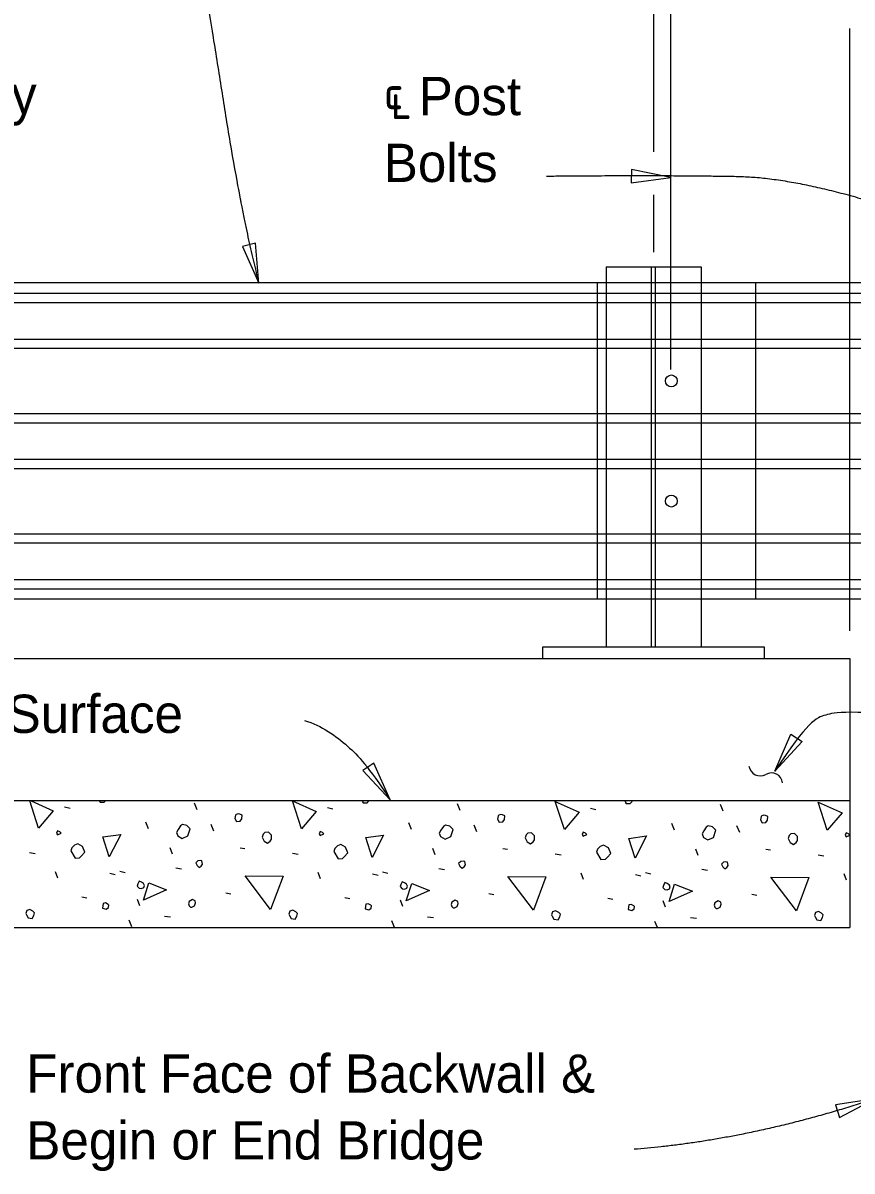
# Model space of a CAD drawing. Extents: x 21526.6 to 21595.9, y 56117 to 56157.3.
# Drawn here: x 21549.82 to 21554.19, y 56132.51 to 56138.56 of the extents above; entities that cross this region are included whole.
import ezdxf

# ---------------------------------------------------------------- set-up
doc = ezdxf.new("R2010")
doc.units = 0
for name, color, linetype in [('AdhocPoint_dp', 7, 'Continuous'), ('Border', 7, 'Continuous'), ('Patterning', 7, 'Continuous'), ('PlotBorder_dp', 7, 'Continuous'), ('SheetBorder_dp', 7, 'Continuous'), ('TextMisc', 7, 'Continuous')]:
    doc.layers.add(name, color=color, linetype=linetype)

msp = doc.modelspace()

# ---------------------------------------------------------------- linework, layer by layer
at = {"layer": 'AdhocPoint_dp'}
for p, q in [((21546.3955, 56135.21), (21554.1792, 56135.21)), ((21554.1792, 56135.21), (21554.1792, 56133.7933)), ((21554.1792, 56134.46), (21546.3955, 56134.46)), ((21546.3955, 56133.7933), (21554.1792, 56133.7933))]:
    msp.add_line(p, q, dxfattribs=at)
at = {"layer": 'Patterning'}
for p, q in [((21553.2368, 56136.733), (21553.2368, 56140.7989)), ((21553.1455, 56139.7166), (21553.1455, 56137.8785)), ((21553.1455, 56137.6522), (21553.1455, 56137.3509)), ((21552.8484, 56137.1891), (21552.8484, 56135.5224)), ((21553.6817, 56137.1891), (21553.6817, 56135.5224)), ((21552.8484, 56137.1336), (21564.1633, 56137.1336)), ((21552.8484, 56137.0853), (21564.1633, 56137.0853)), ((21552.8484, 56136.8925), (21564.1633, 56136.8925)), ((21552.8484, 56136.8443), (21564.1633, 56136.8443)), ((21552.8484, 56136.5003), (21564.1633, 56136.5003)), ((21552.8484, 56136.4521), (21564.1633, 56136.4521)), ((21552.8484, 56136.2593), (21564.1633, 56136.2593)), ((21552.8484, 56136.2112), (21564.1633, 56136.2112)), ((21552.8484, 56135.8672), (21564.1633, 56135.8672)), ((21552.8484, 56135.819), (21564.1633, 56135.819)), ((21552.8484, 56135.6262), (21564.1633, 56135.6262)), ((21552.8484, 56135.5779), (21564.1633, 56135.5779)), ((21550.0437, 56134.4293), (21550.072, 56134.4222)), ((21550.742, 56134.4134), (21550.7278, 56134.4487)), ((21551.4284, 56134.4258), (21551.4567, 56134.4187)), ((21552.1266, 56134.4099), (21552.1125, 56134.4452)), ((21552.8131, 56134.4222), (21552.8413, 56134.4152)), ((21553.5113, 56134.4063), (21553.4972, 56134.4417)), ((21550.4856, 56134.3126), (21550.4715, 56134.348)), ((21550.8297, 56134.3009), (21550.8156, 56134.3362)), ((21551.8703, 56134.3091), (21551.8562, 56134.3444)), ((21552.2144, 56134.2973), (21552.2003, 56134.3327)), ((21553.255, 56134.3056), (21553.2409, 56134.3409)), ((21553.5991, 56134.2938), (21553.5849, 56134.3292)), ((21550.6112, 56134.18), (21550.5988, 56134.2136)), ((21550.9676, 56134.2125), (21550.9924, 56134.209)), ((21551.9958, 56134.1765), (21551.9835, 56134.2101)), ((21549.8587, 56134.1877), (21549.8888, 56134.1824)), ((21551.2434, 56134.1842), (21551.2734, 56134.1789)), ((21552.3523, 56134.209), (21552.377, 56134.2054)), ((21552.6281, 56134.1807), (21552.6581, 56134.1754)), ((21553.3805, 56134.173), (21553.3681, 56134.2066)), ((21553.737, 56134.2054), (21553.7617, 56134.2019)), ((21554.0127, 56134.1771), (21554.0428, 56134.1718)), ((21550.3336, 56134.0899), (21550.3619, 56134.0828)), ((21550.63, 56134.1082), (21550.66, 56134.1029)), ((21552.0147, 56134.1047), (21552.0447, 56134.0994)), ((21553.3993, 56134.1011), (21553.4294, 56134.0958)), ((21550.0072, 56134.0534), (21549.9948, 56134.087)), ((21550.2812, 56134.0799), (21550.3095, 56134.0728)), ((21551.3919, 56134.0499), (21551.3795, 56134.0834)), ((21551.6659, 56134.0764), (21551.6942, 56134.0693)), ((21551.7183, 56134.0864), (21551.7466, 56134.0793)), ((21552.7766, 56134.0463), (21552.7642, 56134.0799)), ((21553.0506, 56134.0728), (21553.0788, 56134.0658)), ((21553.103, 56134.0828), (21553.1313, 56134.0757)), ((21554.1612, 56134.0428), (21554.1489, 56134.0764)), ((21550.8934, 56133.9756), (21550.9199, 56133.9703)), ((21552.278, 56133.9721), (21552.3046, 56133.9668)), ((21553.6627, 56133.9685), (21553.6892, 56133.9632)), ((21550.1345, 56133.9544), (21550.161, 56133.9491)), ((21550.4397, 56133.9073), (21550.4273, 56133.9409)), ((21551.5192, 56133.9509), (21551.5457, 56133.9456)), ((21551.8244, 56133.9038), (21551.812, 56133.9373)), ((21552.9038, 56133.9473), (21552.9304, 56133.942)), ((21553.209, 56133.9002), (21553.1967, 56133.9338)), ((21550.5699, 56133.8536), (21550.6017, 56133.8501)), ((21551.9545, 56133.8501), (21551.9864, 56133.8466)), ((21550.3973, 56133.7977), (21550.3831, 56133.833)), ((21551.7819, 56133.7942), (21551.7678, 56133.8295)), ((21553.1655, 56133.7933), (21553.1525, 56133.826)), ((21553.3392, 56133.8466), (21553.371, 56133.843))]:
    msp.add_line(p, q, dxfattribs=at)
for points in [[(21549.9064, 56134.3168), (21549.8599, 56134.46)], [(21549.8668, 56134.46), (21549.9842, 56134.4087), (21549.9064, 56134.3168)], [(21550.2285, 56134.46), (21550.2311, 56134.454), (21550.2275, 56134.4576)], [(21550.2311, 56134.454), (21550.2523, 56134.454), (21550.2582, 56134.46)], [(21551.2911, 56134.3133), (21551.2434, 56134.46), (21551.3689, 56134.4052), (21551.2911, 56134.3133)], [(21551.6117, 56134.46), (21551.6158, 56134.4505), (21551.6122, 56134.454)], [(21551.6158, 56134.4505), (21551.637, 56134.4505), (21551.6464, 56134.46)], [(21552.6758, 56134.3097), (21552.6281, 56134.4564), (21552.7536, 56134.4016), (21552.6758, 56134.3097)], [(21552.9955, 56134.46), (21552.9951, 56134.4594), (21553.0004, 56134.447), (21552.9969, 56134.4505)], [(21553.0004, 56134.447), (21553.0217, 56134.447), (21553.0323, 56134.4576), (21553.0316, 56134.46)], [(21554.0605, 56134.3062), (21554.0127, 56134.4529), (21554.1383, 56134.3981), (21554.0605, 56134.3062)], [(21550.9393, 56134.3681), (21550.9482, 56134.3521), (21550.9676, 56134.3539), (21550.9765, 56134.3663), (21550.9782, 56134.3857), (21550.9658, 56134.391), (21550.957, 56134.3928), (21550.9464, 56134.3893), (21550.9429, 56134.3857), (21550.9393, 56134.3681)], [(21550.6394, 56134.2755), (21550.6624, 56134.2631), (21550.6925, 56134.2755), (21550.7048, 56134.3126), (21550.6872, 56134.3303), (21550.6642, 56134.3356), (21550.6536, 56134.3285), (21550.6412, 56134.3091), (21550.6324, 56134.2932), (21550.6394, 56134.2755)], [(21552.0241, 56134.272), (21552.0471, 56134.2596), (21552.0771, 56134.272), (21552.0895, 56134.3091), (21552.0718, 56134.3268), (21552.0489, 56134.3321), (21552.0383, 56134.325), (21552.0259, 56134.3056), (21552.017, 56134.2896), (21552.0241, 56134.272)], [(21552.324, 56134.3645), (21552.3328, 56134.3486), (21552.3523, 56134.3504), (21552.3611, 56134.3627), (21552.3629, 56134.3822), (21552.3505, 56134.3875), (21552.3417, 56134.3893), (21552.3311, 56134.3857), (21552.3275, 56134.3822), (21552.324, 56134.3645)], [(21553.7087, 56134.361), (21553.7175, 56134.3451), (21553.737, 56134.3468), (21553.7458, 56134.3592), (21553.7476, 56134.3787), (21553.7352, 56134.384), (21553.7264, 56134.3857), (21553.7158, 56134.3822), (21553.7122, 56134.3787), (21553.7087, 56134.361)], [(21550.0054, 56134.2814), (21550.0249, 56134.2903), (21550.0178, 56134.2973), (21550.0054, 56134.3026), (21550.0001, 56134.2903), (21550.0054, 56134.2814)], [(21550.2788, 56134.1659), (21550.2452, 56134.2702), (21550.3389, 56134.2826), (21550.2788, 56134.1659)], [(21551.0843, 56134.2691), (21551.0949, 56134.2478), (21551.1126, 56134.2372), (21551.1267, 56134.2478), (21551.1338, 56134.2585), (21551.1338, 56134.2797), (21551.1179, 56134.2956), (21551.0984, 56134.2938), (21551.0896, 56134.285), (21551.0843, 56134.2691)], [(21551.3901, 56134.2779), (21551.4096, 56134.2867), (21551.4025, 56134.2938), (21551.3901, 56134.2991), (21551.3848, 56134.2867), (21551.3901, 56134.2779)], [(21551.6635, 56134.1624), (21551.6299, 56134.2667), (21551.7236, 56134.279), (21551.6635, 56134.1624)], [(21552.469, 56134.2655), (21552.4796, 56134.2443), (21552.4973, 56134.2337), (21552.5114, 56134.2443), (21552.5185, 56134.2549), (21552.5185, 56134.2761), (21552.5026, 56134.292), (21552.4831, 56134.2903), (21552.4743, 56134.2814), (21552.469, 56134.2655)], [(21552.7748, 56134.2744), (21552.7942, 56134.2832), (21552.7872, 56134.2903), (21552.7748, 56134.2956), (21552.7695, 56134.2832), (21552.7748, 56134.2744)], [(21553.0482, 56134.1588), (21553.0146, 56134.2631), (21553.1083, 56134.2755), (21553.0482, 56134.1588)], [(21553.4088, 56134.2684), (21553.4318, 56134.2561), (21553.4618, 56134.2684), (21553.4742, 56134.3056), (21553.4565, 56134.3232), (21553.4335, 56134.3285), (21553.4229, 56134.3215), (21553.4106, 56134.302), (21553.4017, 56134.2861), (21553.4088, 56134.2684)], [(21553.8536, 56134.262), (21553.8643, 56134.2408), (21553.8819, 56134.2302), (21553.8961, 56134.2408), (21553.9031, 56134.2514), (21553.9031, 56134.2726), (21553.8872, 56134.2885), (21553.8678, 56134.2867), (21553.8589, 56134.2779), (21553.8536, 56134.262)], [(21554.1595, 56134.2708), (21554.1789, 56134.2797), (21554.1718, 56134.2867), (21554.1595, 56134.292), (21554.1542, 56134.2797), (21554.1595, 56134.2708)], [(21550.0761, 56134.1966), (21550.0991, 56134.1595), (21550.1221, 56134.1612), (21550.1309, 56134.1701), (21550.1504, 56134.1895), (21550.138, 56134.2196), (21550.1133, 56134.2337), (21550.0956, 56134.2266), (21550.0815, 56134.2125), (21550.0761, 56134.1966)], [(21551.4608, 56134.193), (21551.4838, 56134.1559), (21551.5068, 56134.1577), (21551.5156, 56134.1665), (21551.5351, 56134.186), (21551.5227, 56134.216), (21551.4979, 56134.2302), (21551.4803, 56134.2231), (21551.4661, 56134.209), (21551.4608, 56134.193)], [(21552.8455, 56134.1895), (21552.8685, 56134.1524), (21552.8915, 56134.1542), (21552.9003, 56134.163), (21552.9197, 56134.1824), (21552.9074, 56134.2125), (21552.8826, 56134.2266), (21552.8649, 56134.2196), (21552.8508, 56134.2054), (21552.8455, 56134.1895)], [(21550.7413, 56134.1206), (21550.7519, 56134.11), (21550.7626, 56134.117), (21550.7696, 56134.1276), (21550.7661, 56134.1453), (21550.7573, 56134.1471), (21550.7449, 56134.1453), (21550.7343, 56134.1347), (21550.7413, 56134.1206)], [(21552.126, 56134.117), (21552.1366, 56134.1064), (21552.1472, 56134.1135), (21552.1543, 56134.1241), (21552.1508, 56134.1418), (21552.1419, 56134.1435), (21552.1296, 56134.1418), (21552.1189, 56134.1312), (21552.126, 56134.117)], [(21553.5107, 56134.1135), (21553.5213, 56134.1029), (21553.5319, 56134.11), (21553.539, 56134.1206), (21553.5354, 56134.1382), (21553.5266, 56134.14), (21553.5142, 56134.1382), (21553.5036, 56134.1276), (21553.5107, 56134.1135)], [(21550.4361, 56134.0015), (21550.4485, 56133.9997), (21550.4609, 56134.005), (21550.4644, 56134.0156), (21550.4591, 56134.0245), (21550.4485, 56134.0316), (21550.4361, 56134.0369), (21550.4291, 56134.0227), (21550.4255, 56134.0121), (21550.4361, 56134.0015)], [(21550.4585, 56133.9367), (21550.4868, 56134.0286), (21550.5805, 56133.9915), (21550.4585, 56133.9367)], [(21551.1285, 56133.889), (21550.9941, 56134.0658), (21551.1939, 56134.064), (21551.1285, 56133.889)], [(21551.8208, 56133.998), (21551.8332, 56133.9962), (21551.8456, 56134.0015), (21551.8491, 56134.0121), (21551.8438, 56134.0209), (21551.8332, 56134.028), (21551.8208, 56134.0333), (21551.8138, 56134.0192), (21551.8102, 56134.0086), (21551.8208, 56133.998)], [(21552.5132, 56133.8855), (21552.3788, 56134.0622), (21552.5786, 56134.0605), (21552.5132, 56133.8855)], [(21553.2055, 56133.9944), (21553.2179, 56133.9927), (21553.2302, 56133.998), (21553.2338, 56134.0086), (21553.2285, 56134.0174), (21553.2179, 56134.0245), (21553.2055, 56134.0298), (21553.1984, 56134.0156), (21553.1949, 56134.005), (21553.2055, 56133.9944)], [(21553.8978, 56133.8819), (21553.7635, 56134.0587), (21553.9632, 56134.0569), (21553.8978, 56133.8819)], [(21551.8432, 56133.9332), (21551.8715, 56134.0251), (21551.9652, 56133.988), (21551.8432, 56133.9332)], [(21553.2279, 56133.9296), (21553.2561, 56134.0216), (21553.3498, 56133.9844), (21553.2279, 56133.9296)], [(21550.2423, 56133.8961), (21550.2618, 56133.8908), (21550.2741, 56133.8996), (21550.2759, 56133.912), (21550.2724, 56133.9155), (21550.2582, 56133.9226), (21550.2459, 56133.9208), (21550.2441, 56133.9084), (21550.2423, 56133.8961)], [(21550.706, 56133.9014), (21550.7131, 56133.9014), (21550.7272, 56133.9084), (21550.7325, 56133.9243), (21550.7307, 56133.9332), (21550.7166, 56133.9403), (21550.6989, 56133.9296), (21550.6954, 56133.919), (21550.6989, 56133.9084), (21550.706, 56133.9014)], [(21551.627, 56133.8925), (21551.6464, 56133.8872), (21551.6588, 56133.8961), (21551.6606, 56133.9084), (21551.657, 56133.912), (21551.6429, 56133.919), (21551.6305, 56133.9173), (21551.6288, 56133.9049), (21551.627, 56133.8925)], [(21552.0907, 56133.8978), (21552.0977, 56133.8978), (21552.1119, 56133.9049), (21552.1172, 56133.9208), (21552.1154, 56133.9296), (21552.1013, 56133.9367), (21552.0836, 56133.9261), (21552.0801, 56133.9155), (21552.0836, 56133.9049), (21552.0907, 56133.8978)], [(21553.0117, 56133.889), (21553.0311, 56133.8837), (21553.0435, 56133.8925), (21553.0453, 56133.9049), (21553.0417, 56133.9084), (21553.0276, 56133.9155), (21553.0152, 56133.9137), (21553.0134, 56133.9014), (21553.0117, 56133.889)], [(21553.4753, 56133.8943), (21553.4824, 56133.8943), (21553.4966, 56133.9014), (21553.5019, 56133.9173), (21553.5001, 56133.9261), (21553.4859, 56133.9332), (21553.4683, 56133.9226), (21553.4647, 56133.912), (21553.4683, 56133.9014), (21553.4753, 56133.8943)], [(21549.8428, 56133.8607), (21549.8516, 56133.8448), (21549.8729, 56133.8413), (21549.8817, 56133.8572), (21549.8852, 56133.8713), (21549.8764, 56133.8801), (21549.8605, 56133.889), (21549.8446, 56133.8837), (21549.8393, 56133.8678), (21549.8428, 56133.8607)], [(21551.2275, 56133.8572), (21551.2363, 56133.8413), (21551.2575, 56133.8377), (21551.2664, 56133.8536), (21551.2699, 56133.8678), (21551.2611, 56133.8766), (21551.2452, 56133.8855), (21551.2292, 56133.8801), (21551.2239, 56133.8642), (21551.2275, 56133.8572)], [(21552.6122, 56133.8536), (21552.621, 56133.8377), (21552.6422, 56133.8342), (21552.651, 56133.8501), (21552.6546, 56133.8642), (21552.6457, 56133.8731), (21552.6298, 56133.8819), (21552.6139, 56133.8766), (21552.6086, 56133.8607), (21552.6122, 56133.8536)], [(21553.9968, 56133.8501), (21554.0057, 56133.8342), (21554.0269, 56133.8307), (21554.0357, 56133.8466), (21554.0393, 56133.8607), (21554.0304, 56133.8695), (21554.0145, 56133.8784), (21553.9986, 56133.8731), (21553.9933, 56133.8572), (21553.9968, 56133.8501)]]:
    msp.add_lwpolyline(points, dxfattribs=at)
at = {"layer": 'PlotBorder_dp'}
msp.add_line((21554.1792, 56135.3555), (21554.1792, 56138.5276), dxfattribs=at)
for points in [[(21553.2368, 56137.7435), (21553.03, 56137.7865), (21553.0274, 56137.7159)], [(21551.0667, 56137.1865), (21551.0486, 56137.397), (21550.9803, 56137.3793)], [(21553.7845, 56134.6171), (21553.8687, 56134.8109), (21553.9278, 56134.7723)], [(21551.7585, 56134.4667), (21551.672, 56134.6594), (21551.6134, 56134.6201)], [(21554.3117, 56132.8915), (21554.1029, 56132.8596), (21554.1251, 56132.7926)]]:
    msp.add_lwpolyline(points, close=True, dxfattribs=at)
for centre, start, end in [((21553.707, 56134.6515), 187.95358, 299.6808), ((21553.766, 56134.5479), 7.95358, 119.6808)]:
    msp.add_arc(centre, 0.0596, start, end, dxfattribs=at)
for points, degree in [([(21550.1903, 56139.7107), (21550.4589, 56139.7107), (21550.5932, 56139.5622), (21550.7699, 56138.8551), (21550.9678, 56137.5683), (21551.0667, 56137.1865)], 2), ([(21552.581, 56137.751), (21553.1726, 56137.7569), (21553.9973, 56137.7421), (21554.7081, 56137.4746)], 2), ([(21554.6745, 56134.9046), (21554.1531, 56134.9384), (21554.0496, 56134.9162), (21553.9557, 56134.8796), (21553.7845, 56134.6171)], 3), ([(21551.3063, 56134.8834), (21551.3975, 56134.859), (21551.55, 56134.7437), (21551.6378, 56134.647), (21551.7585, 56134.4666)], 3), ([(21554.3117, 56132.8915), (21553.648, 56132.6719), (21553.044, 56132.6254)], 2)]:
    msp.add_open_spline(points, degree=degree, dxfattribs=at)
at = {"layer": 'SheetBorder_dp'}
for p, q in [((21553.1351, 56135.2724), (21553.1351, 56137.2724)), ((21553.1559, 56135.2724), (21553.1559, 56137.2724)), ((21564.1633, 56137.1891), (21552.8484, 56137.1891)), ((21552.8955, 56137.1891), (21552.8955, 56135.5224)), ((21553.3955, 56137.1891), (21553.3955, 56135.5224)), ((21564.1633, 56135.5224), (21552.8484, 56135.5224))]:
    msp.add_line(p, q, dxfattribs=at)
at = {"layer": 'TextMisc'}
for p, q in [((21552.8955, 56137.2724), (21553.3955, 56137.2724)), ((21552.8955, 56137.2724), (21552.8955, 56137.1892)), ((21553.3955, 56137.2724), (21553.3955, 56137.1891)), ((21552.8484, 56137.1892), (21546.3955, 56137.1892)), ((21546.3955, 56137.1336), (21552.8484, 56137.1336)), ((21546.3955, 56137.0854), (21552.8484, 56137.0854)), ((21546.3955, 56136.8926), (21552.8484, 56136.8926)), ((21546.3955, 56136.8444), (21552.8484, 56136.8444)), ((21546.3955, 56136.5004), (21552.8484, 56136.5004)), ((21546.3955, 56136.4522), (21552.8484, 56136.4522)), ((21546.3955, 56136.2594), (21552.8484, 56136.2594)), ((21546.3955, 56136.2112), (21552.8484, 56136.2112)), ((21546.3955, 56135.8673), (21552.8484, 56135.8673)), ((21546.3955, 56135.8191), (21552.8484, 56135.8191)), ((21546.3955, 56135.6262), (21552.8484, 56135.6262)), ((21546.3955, 56135.578), (21552.8484, 56135.578)), ((21552.8484, 56135.5225), (21546.3955, 56135.5225)), ((21552.8955, 56135.5224), (21552.8955, 56135.2724)), ((21553.3955, 56135.5224), (21553.3955, 56135.2724)), ((21552.5621, 56135.2724), (21553.7288, 56135.2724)), ((21552.5621, 56135.2099), (21552.5621, 56135.2724)), ((21552.8955, 56135.2724), (21553.3955, 56135.2724)), ((21553.7288, 56135.2724), (21553.7288, 56135.2099)), ((21552.5621, 56135.2099), (21553.7288, 56135.2099))]:
    msp.add_line(p, q, dxfattribs=at)
for centre in [(21553.2392, 56136.6723), (21553.2392, 56136.0392)]:
    msp.add_circle(centre, 0.0312, dxfattribs=at)

# ---------------------------------------------------------------- texts
at = {"layer": 'Border'}
msp.add_text('Final Riding Surface', height=0.2016, dxfattribs=at).set_placement((21548.2396, 56134.8183))
at = {"layer": 'PlotBorder_dp'}
for s, p in [('Asphalt Overlay', (21547.9936, 56138.0774)), ('℄ Post ', (21551.7244, 56138.0718)), ('Bolts', (21551.7244, 56137.7198)), ('Front Face of Backwall &', (21549.8416, 56132.9237)), ('Begin or End Bridge', (21549.8416, 56132.5717))]:
    msp.add_text(s, height=0.2016, dxfattribs=at).set_placement(p)

doc.saveas('drawing.dxf')
